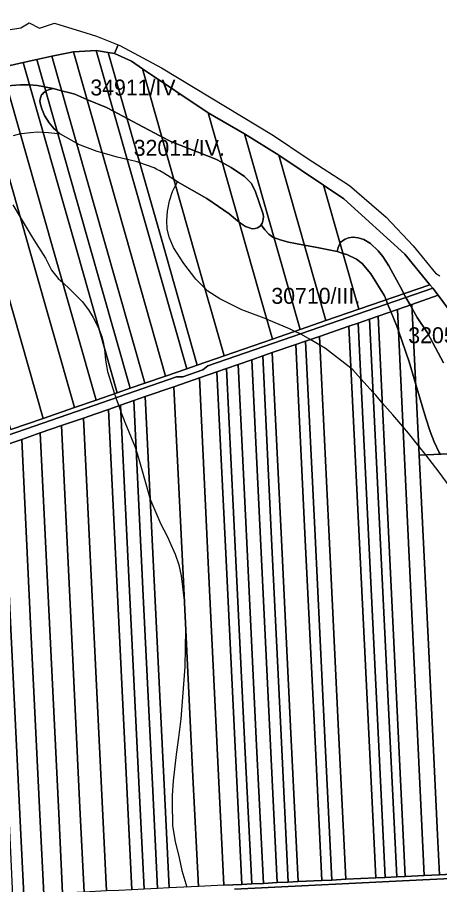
# Model space of a CAD drawing. Extents: x -521939 to -516426, y -1197857 to -1189551.
# Drawn here: x -520134 to -519736, y -1190609 to -1189793 of the extents above; entities that cross this region are included whole.
import ezdxf

# ---------------------------------------------------------------- set-up
doc = ezdxf.new("R2010")
doc.units = 0
for name, color, linetype in [('95560013', 7, 'Continuous'), ('95630013', 7, 'Continuous'), ('95640013', 7, 'Continuous'), ('95660013', 7, 'Continuous')]:
    doc.layers.add(name, color=color, linetype=linetype)

msp = doc.modelspace()

# ---------------------------------------------------------------- linework, layer by layer
at = {"layer": '95560013'}
for points in [[(-519994.39, -1190130.64), (-520013.93, -1190137.37), (-520052.62, -1190001.75), (-520101.68, -1189829.78), (-520081.3, -1189825.57), (-520032.2, -1189997.92)], [(-519974.5, -1190123.76), (-519994.39, -1190130.64), (-520032.2, -1189997.92), (-520081.3, -1189825.57), (-520059.78, -1189824.56), (-520011.22, -1189994.93)], [(-520059.78, -1189824.56), (-520048.37, -1189826.26), (-519998.68, -1190000.59), (-519964.55, -1190120.33), (-519974.5, -1190123.76), (-520011.22, -1189994.93)], [(-520016.21, -1189841.8), (-519966.48, -1190016.23), (-519939.29, -1190111.6), (-519964.55, -1190120.33), (-519998.68, -1190000.59), (-520048.37, -1189826.26), (-520042.45, -1189827.13), (-520026.64, -1189834.56)], [(-520027.72, -1190142.13), (-520039.96, -1190146.38), (-520078.09, -1190012.6), (-520128.53, -1189835.63), (-520115.8, -1189832.85), (-520068.24, -1189999.85)], [(-520013.93, -1190137.37), (-520027.72, -1190142.13), (-520068.24, -1189999.85), (-520115.8, -1189832.85), (-520101.68, -1189829.78), (-520052.62, -1190001.75)], [(-520170.1, -1189845.48), (-520148.93, -1189840.36), (-520099.85, -1190012.63), (-520059.79, -1190153.24), (-520080.27, -1190160.27), (-520121.1, -1190017.19)], [(-520078.09, -1190012.6), (-520039.96, -1190146.38), (-520059.79, -1190153.24), (-520099.85, -1190012.63), (-520148.93, -1189840.36), (-520128.53, -1189835.63)], [(-519893.79, -1190095.91), (-519939.29, -1190111.6), (-519966.48, -1190016.23), (-520016.21, -1189841.8), (-519954.44, -1189883.11), (-519905.92, -1190053.35)], [(-520109.85, -1190170.52), (-520140.18, -1190180.98), (-520187.21, -1190016.15), (-520236.34, -1189843.96), (-520214.4, -1189848.97), (-520201.29, -1189849.7), (-520152.05, -1190022.46)], [(-520201.29, -1189849.7), (-520197.95, -1189849.92), (-520181.77, -1189848.28), (-520170.1, -1189845.48), (-520121.1, -1190017.19), (-520080.27, -1190160.27), (-520109.85, -1190170.52), (-520152.05, -1190022.46)], [(-519867.74, -1190086.89), (-519893.79, -1190095.91), (-519905.92, -1190053.35), (-519954.44, -1189883.11), (-519920.2, -1189902.73)], [(-519920.2, -1189902.73), (-519887.92, -1189922.82), (-519843.42, -1190078.49), (-519867.74, -1190086.89)], [(-519812.48, -1190067.72), (-519843.42, -1190078.49), (-519887.92, -1189922.82), (-519845.8, -1189951.09)], [(-519745.61, -1190044.71), (-519812.48, -1190067.72), (-519845.8, -1189951.09), (-519826.71, -1189964.04), (-519769.14, -1190015.86)], [(-519737.67, -1190054.66), (-519717.63, -1190081.69), (-519692.57, -1190119.33), (-519690.61, -1190124.71), (-519691.71, -1190131.91), (-519714.39, -1190170.65), (-519713.62, -1190184.5), (-519709.23, -1190202.58), (-519715.93, -1190202.95), (-519727.94, -1190203.65), (-519755.55, -1190205.15), (-519762.5, -1190063.2)], [(-519768.71, -1190601.2), (-519785.79, -1190251), (-519794.41, -1190074.26), (-519785.22, -1190071.01), (-519776.17, -1190067.93), (-519750.81, -1190600.31)], [(-519776.17, -1190067.93), (-519762.5, -1190063.2), (-519755.55, -1190205.15), (-519747.01, -1190383.02), (-519738.41, -1190562.14), (-519736.61, -1190599.63), (-519750.81, -1190600.31)], [(-519793.61, -1190256.71), (-519784.84, -1190436.43), (-519776.78, -1190601.6), (-519787.62, -1190602.12), (-519795.52, -1190440.08), (-519804.28, -1190260.4), (-519813.04, -1190080.72), (-519802.38, -1190076.99)], [(-519776.78, -1190601.6), (-519784.84, -1190436.43), (-519793.61, -1190256.71), (-519802.38, -1190076.99), (-519794.41, -1190074.26), (-519785.79, -1190251), (-519768.71, -1190601.2)], [(-519821.87, -1190083.74), (-519813.16, -1190262.35), (-519804.45, -1190440.96), (-519796.57, -1190602.55), (-519824.74, -1190603.91), (-519831.84, -1190457.96), (-519841.06, -1190268.43), (-519849.58, -1190093.29)], [(-519813.04, -1190080.72), (-519804.28, -1190260.4), (-519795.52, -1190440.08), (-519787.62, -1190602.12), (-519796.57, -1190602.55), (-519804.45, -1190440.96), (-519813.16, -1190262.35), (-519821.87, -1190083.74)], [(-519831.84, -1190457.96), (-519824.74, -1190603.91), (-519837.89, -1190604.57), (-519844.74, -1190464.08), (-519853.67, -1190280.93), (-519862.6, -1190097.78), (-519849.58, -1190093.29), (-519841.06, -1190268.43)], [(-519871.89, -1190101.04), (-519863.24, -1190278.4), (-519854.65, -1190454.53), (-519847.31, -1190605.03), (-519869.68, -1190606.1), (-519876.8, -1190460.09), (-519885.36, -1190284.55), (-519893.94, -1190108.6)], [(-519862.6, -1190097.78), (-519853.67, -1190280.93), (-519844.74, -1190464.08), (-519837.89, -1190604.57), (-519847.31, -1190605.03), (-519854.65, -1190454.53), (-519863.24, -1190278.4), (-519871.89, -1190101.04)], [(-519878.91, -1190606.55), (-519889.29, -1190607.07), (-519895.57, -1190478.17), (-519904.42, -1190296.52), (-519913.25, -1190115.28), (-519903.02, -1190111.63), (-519894.32, -1190290.22), (-519885.62, -1190468.81)], [(-519869.68, -1190606.1), (-519878.91, -1190606.55), (-519885.62, -1190468.81), (-519894.32, -1190290.22), (-519903.02, -1190111.63), (-519893.94, -1190108.6), (-519885.36, -1190284.55), (-519876.8, -1190460.09)], [(-519917.36, -1190300.23), (-519908.7, -1190478.11), (-519902.39, -1190607.72), (-519913.35, -1190608.25), (-519919.36, -1190484.84), (-519928.16, -1190304.14), (-519936.96, -1190123.44), (-519926.15, -1190119.68)], [(-519913.25, -1190115.28), (-519904.42, -1190296.52), (-519895.57, -1190478.17), (-519889.29, -1190607.07), (-519902.39, -1190607.72), (-519908.7, -1190478.11), (-519917.36, -1190300.23), (-519926.15, -1190119.68)], [(-519946.2, -1190126.69), (-519937.53, -1190303.61), (-519928.59, -1190486.04), (-519922.58, -1190608.68), (-519939.51, -1190609.57), (-519945.13, -1190493.52), (-519953.89, -1190312.63), (-519962.62, -1190132.36)], [(-519928.16, -1190304.14), (-519919.36, -1190484.84), (-519913.35, -1190608.25), (-519922.58, -1190608.68), (-519928.59, -1190486.04), (-519937.53, -1190303.61), (-519946.2, -1190126.69), (-519936.96, -1190123.44)], [(-519962.62, -1190132.36), (-519953.89, -1190312.63), (-519945.13, -1190493.52), (-519939.51, -1190609.57), (-519963.54, -1190610.7), (-519968.64, -1190507.1), (-519977.66, -1190323.87), (-519986.68, -1190140.64)], [(-519986.68, -1190140.64), (-519977.66, -1190323.87), (-519968.64, -1190507.1), (-519963.54, -1190610.7), (-519991.19, -1190612.07), (-519996.22, -1190508.35), (-520004.91, -1190329.16), (-520013.6, -1190149.97)], [(-520013.6, -1190149.97), (-520004.91, -1190329.16), (-519996.22, -1190508.35), (-519991.19, -1190612.07), (-520001.96, -1190612.59), (-520006.44, -1190520.8), (-520015.4, -1190337.22), (-520024.36, -1190153.64)], [(-520048.21, -1190161.91), (-520036.77, -1190157.93), (-520028.27, -1190332.71), (-520019.52, -1190512.63), (-520014.63, -1190613.18), (-520026.22, -1190613.75)], [(-520024.36, -1190153.64), (-520015.4, -1190337.22), (-520006.44, -1190520.8), (-520001.96, -1190612.59), (-520014.63, -1190613.18), (-520019.52, -1190512.63), (-520028.27, -1190332.71), (-520036.77, -1190157.93)], [(-520050.2, -1190614.9), (-520071.81, -1190170.12), (-520060.18, -1190166.05), (-520048.21, -1190161.91), (-520026.22, -1190613.75), (-520038.38, -1190614.32)], [(-520071.18, -1190615.91), (-520075.05, -1190536.24), (-520083.71, -1190357.96), (-520092.49, -1190177.21), (-520071.81, -1190170.12), (-520050.2, -1190614.9)], [(-520091.44, -1190616.96), (-520109.18, -1190617.83), (-520112.49, -1190549.67), (-520121.22, -1190369.9), (-520129.95, -1190190.13), (-520112.49, -1190184.08), (-520103.79, -1190362.99), (-520095.09, -1190541.9)], [(-520092.49, -1190177.21), (-520083.71, -1190357.96), (-520075.05, -1190536.24), (-520071.18, -1190615.91), (-520091.44, -1190616.96), (-520095.09, -1190541.9), (-520103.79, -1190362.99), (-520112.49, -1190184.08)], [(-520109.18, -1190617.83), (-520127.96, -1190618.79), (-520131.03, -1190555.62), (-520139.79, -1190375.37), (-520148.48, -1190196.56), (-520129.95, -1190190.13), (-520121.22, -1190369.9), (-520112.49, -1190549.67)], [(-520127.96, -1190618.79), (-520138.15, -1190619.38), (-520142.13, -1190537.41), (-520144.39, -1190490.9), (-520147.18, -1190433.47), (-520148.49, -1190406.47), (-520149.36, -1190388.6), (-520150.33, -1190368.63), (-520158.52, -1190200.01), (-520148.48, -1190196.56), (-520139.79, -1190375.37), (-520131.03, -1190555.62)], [(-519727.94, -1190203.65), (-519719.31, -1190382.05), (-519710.68, -1190560.45), (-519708.85, -1190598.28), (-519736.61, -1190599.63), (-519738.41, -1190562.14), (-519747.01, -1190383.02), (-519755.55, -1190205.15)]]:
    msp.add_lwpolyline(points, close=True, dxfattribs=at)
at = {"layer": '95630013'}
msp.add_lwpolyline([(-519717.63, -1190081.69), (-519737.67, -1190054.66), (-519742.92, -1190048.01), (-519745.61, -1190044.71), (-519769.14, -1190015.86), (-519826.71, -1189964.04), (-519845.8, -1189951.09), (-519887.92, -1189922.82), (-519920.2, -1189902.73), (-519954.44, -1189883.11), (-520016.21, -1189841.8), (-520026.64, -1189834.56), (-520042.45, -1189827.13), (-520038.96, -1189819.12), (-520037.43, -1189819.73), (-519998.21, -1189840.6), (-519892.81, -1189904.25), (-519861, -1189925.67), (-519821.23, -1189951.29), (-519786.78, -1189981.15), (-519761.19, -1190007.99), (-519740.21, -1190033.91), (-519736.08, -1190036.41)], dxfattribs=at)
at = {"layer": '95640013'}
for points in [[(-520140.61, -1189804.59), (-520130.63, -1189803.21), (-520122.95, -1189798.51), (-520113.06, -1189803.55), (-520099.05, -1189798.82), (-520069.51, -1189807.88), (-520059.38, -1189810.98), (-520038.96, -1189819.12), (-520042.45, -1189827.13), (-520048.37, -1189826.26), (-520059.78, -1189824.56), (-520081.3, -1189825.57), (-520101.68, -1189829.78), (-520115.8, -1189832.85), (-520128.53, -1189835.63), (-520148.93, -1189840.36)], [(-520140.18, -1190180.98), (-520109.85, -1190170.52), (-520080.27, -1190160.27), (-520059.79, -1190153.24), (-520039.96, -1190146.38), (-520027.72, -1190142.13), (-520013.93, -1190137.37), (-519994.39, -1190130.64), (-519974.5, -1190123.76), (-519964.55, -1190120.33), (-519939.29, -1190111.6), (-519893.79, -1190095.91), (-519867.74, -1190086.89), (-519843.42, -1190078.49), (-519812.48, -1190067.72), (-519745.61, -1190044.71), (-519742.92, -1190048.01), (-519787.45, -1190063.39), (-519954.51, -1190121.09), (-519959.21, -1190124.83), (-519978.27, -1190131.41), (-519984.27, -1190131.37), (-520061.95, -1190158.2), (-520231.96, -1190216.92)], [(-520231.96, -1190216.92), (-520061.95, -1190158.2), (-519984.27, -1190131.37), (-519978.27, -1190131.41), (-519959.21, -1190124.83), (-519954.51, -1190121.09), (-519787.45, -1190063.39), (-519742.92, -1190048.01), (-519737.67, -1190054.66), (-519762.5, -1190063.2), (-519776.17, -1190067.93), (-519785.22, -1190071.01), (-519794.41, -1190074.26), (-519802.38, -1190076.99), (-519813.04, -1190080.72), (-519821.87, -1190083.74), (-519849.58, -1190093.29), (-519862.6, -1190097.78), (-519871.89, -1190101.04), (-519893.94, -1190108.6), (-519903.02, -1190111.63), (-519913.25, -1190115.28), (-519926.15, -1190119.68), (-519936.96, -1190123.44), (-519946.2, -1190126.69), (-519962.62, -1190132.36), (-519986.68, -1190140.64), (-520013.6, -1190149.97), (-520024.36, -1190153.64), (-520036.77, -1190157.93), (-520048.21, -1190161.91), (-520060.18, -1190166.05), (-520071.81, -1190170.12), (-520092.49, -1190177.21), (-520112.49, -1190184.08), (-520129.95, -1190190.13), (-520148.48, -1190196.56)], [(-519939.51, -1190609.57), (-519922.58, -1190608.68), (-519913.35, -1190608.25), (-519902.39, -1190607.72), (-519889.29, -1190607.07), (-519878.91, -1190606.55), (-519869.68, -1190606.1), (-519847.31, -1190605.03), (-519837.89, -1190604.57), (-519824.74, -1190603.91), (-519796.57, -1190602.55), (-519787.62, -1190602.12), (-519776.78, -1190601.6), (-519768.71, -1190601.2), (-519750.81, -1190600.31), (-519736.61, -1190599.63), (-519708.85, -1190598.28), (-519697.37, -1190597.74), (-519693.24, -1190597.51), (-519688.47, -1190592.56), (-519688.62, -1190605.97), (-519693.24, -1190601.52), (-519752.34, -1190604.4), (-519929.64, -1190613.04)], [(-519929.64, -1190613.04), (-519752.34, -1190604.4), (-519693.24, -1190601.52), (-519688.62, -1190605.97), (-519688.65, -1190609.3)]]:
    msp.add_lwpolyline(points, dxfattribs=at)
at = {"layer": '95660013'}
for points in [[(-520244.78, -1189796.37), (-520218.36, -1189793.23), (-520217.67, -1189803.44), (-520212.85, -1189810.43), (-520197.6, -1189811.81), (-520167.44, -1189803.44), (-520140.61, -1189804.59), (-520130.63, -1189803.21), (-520122.95, -1189798.51), (-520113.06, -1189803.55), (-520099.05, -1189798.82), (-520069.51, -1189807.88), (-520059.38, -1189810.98), (-520038.96, -1189819.12), (-520037.43, -1189819.73), (-519998.21, -1189840.6), (-519892.81, -1189904.25), (-519861, -1189925.67), (-519821.23, -1189951.29), (-519786.78, -1189981.15), (-519761.19, -1190007.99), (-519740.21, -1190033.91), (-519736.08, -1190036.41)], [(-520144.05, -1189857.5), (-520131.11, -1189856.69), (-520122.71, -1189856.69), (-520122.52, -1189856.71), (-520115.01, -1189857.39), (-520110.12, -1189858.32), (-520108.45, -1189858.64), (-520100.32, -1189860.19), (-520103.93, -1189861), (-520107.02, -1189862.4), (-520107.32, -1189862.62), (-520109.47, -1189864.15), (-520110.17, -1189865.02), (-520111.17, -1189866.25), (-520112.33, -1189869.05), (-520112.86, -1189871.91), (-520112.33, -1189875.35), (-520110.93, -1189879.43), (-520108.31, -1189885.55), (-520104.11, -1189892.32), (-520099.27, -1189898.04), (-520096.57, -1189900.36), (-520093.44, -1189903.05), (-520095.89, -1189902.76), (-520104.58, -1189901.71), (-520109.75, -1189901.54), (-520110.57, -1189901.51), (-520115.07, -1189901.36), (-520121.72, -1189901.94), (-520130, -1189902.64), (-520131.1, -1189902.94), (-520137.82, -1189904.74)], [(-519732.61, -1190118.14), (-519747.89, -1190090.02), (-519757.69, -1190075.44), (-519762.31, -1190067.1), (-519764.15, -1190063.77), (-519768.07, -1190056.7), (-519770.05, -1190053.12), (-519771.45, -1190050.6), (-519784.16, -1190026.92), (-519789.76, -1190018.06), (-519794.31, -1190012.69), (-519801.43, -1190005.93), (-519807.84, -1190002.19), (-519810.96, -1190001.18), (-519813.21, -1190000.45), (-519817.67, -1190000), (-519817.87, -1189999.98), (-519817.99, -1190000), (-519822.07, -1190000.68), (-519825.34, -1190001.73), (-519827.9, -1190003.36), (-519829.3, -1190004.76), (-519830.1, -1190006.03), (-519830.7, -1190006.98), (-519831.87, -1190009.78), (-519832.98, -1190013.57), (-519850.18, -1190010.07), (-519863.73, -1190007.43), (-519863.95, -1190007.39), (-519872.02, -1190005.91), (-519878.64, -1190004.7), (-519886.57, -1190002.6), (-519892.37, -1190000.43), (-519893.11, -1190000.15), (-519893.32, -1190000), (-519897.31, -1189997.12), (-519900.92, -1189993.16), (-519904.3, -1189988.49), (-519903.43, -1189986.86), (-519902.85, -1189984.99), (-519902.5, -1189982.89), (-519902.38, -1189980.73), (-519902.5, -1189978.46), (-519909.96, -1189956.53), (-519913.93, -1189949.3), (-519917.38, -1189945.71), (-519919.99, -1189943), (-519932.82, -1189934.37), (-519941.11, -1189929.88), (-519947.05, -1189926.67), (-519989.51, -1189910.11), (-519998.02, -1189905.61), (-520000, -1189904.56), (-520030.68, -1189888.33), (-520043.54, -1189881.53), (-520049.93, -1189878.15), (-520068.54, -1189870.36), (-520080.02, -1189865.55), (-520084.6, -1189864.32), (-520092.43, -1189862.21), (-520094.72, -1189861.59), (-520100.32, -1189860.19), (-520108.45, -1189858.64), (-520110.12, -1189858.32), (-520115.01, -1189857.39), (-520122.52, -1189856.71), (-520122.71, -1189856.69), (-520131.11, -1189856.69), (-520144.05, -1189857.5)], [(-519726.41, -1190235.21), (-519736.87, -1190220.95), (-519749.51, -1190204.82), (-519755.97, -1190196.57), (-519765.56, -1190184.33), (-519770.92, -1190178.17), (-519780.53, -1190167.11), (-519790.44, -1190155.72), (-519796.59, -1190148.64), (-519799.02, -1190145.92), (-519810.49, -1190133.08), (-519818.05, -1190124.61), (-519819.95, -1190123.16), (-519843.94, -1190104.78), (-519849.17, -1190101.67), (-519858.25, -1190096.28), (-519866.34, -1190091.48), (-519867.39, -1190091), (-519872.66, -1190088.59), (-519877.71, -1190086.29), (-519897.31, -1190077.89), (-519899.12, -1190077.21), (-519922.73, -1190068.33), (-519943.26, -1190058.07), (-519954.69, -1190050.83), (-519957.41, -1190048.06), (-519965.89, -1190039.4), (-519977.32, -1190024.71), (-519987.12, -1190009.54), (-519990.85, -1190000.68), (-519991.02, -1190000), (-519992.95, -1189992.28), (-519993.42, -1189984.58), (-519992.72, -1189975.48), (-519990.85, -1189965.92), (-519987.82, -1189957.06), (-519984.97, -1189951.39), (-519983.21, -1189947.9), (-519986.58, -1189945.76), (-519996.04, -1189939.73), (-520000, -1189937.6), (-520002.57, -1189936.22), (-520005.14, -1189934.84), (-520018.77, -1189930.1), (-520021.24, -1189929.24), (-520029.15, -1189927.38), (-520030.57, -1189927.05), (-520040.13, -1189924.8), (-520054.19, -1189920.74), (-520058.91, -1189919.38), (-520077.11, -1189912.38), (-520078.31, -1189911.69), (-520093.44, -1189903.05), (-520095.89, -1189902.76), (-520104.58, -1189901.71), (-520109.75, -1189901.54), (-520110.57, -1189901.51), (-520115.07, -1189901.36), (-520121.72, -1189901.94), (-520130, -1189902.64), (-520131.1, -1189902.94), (-520137.82, -1189904.74)], [(-519726.41, -1190235.21), (-519736.87, -1190220.95), (-519749.51, -1190204.82), (-519755.97, -1190196.57), (-519765.56, -1190184.33), (-519770.92, -1190178.17), (-519780.53, -1190167.11), (-519790.44, -1190155.72), (-519796.59, -1190148.64), (-519799.02, -1190145.92), (-519810.49, -1190133.08), (-519818.05, -1190124.61), (-519819.95, -1190123.16), (-519843.94, -1190104.78), (-519849.17, -1190101.67), (-519858.25, -1190096.28), (-519866.34, -1190091.48), (-519867.39, -1190091), (-519872.66, -1190088.59), (-519877.71, -1190086.29), (-519897.31, -1190077.89), (-519899.12, -1190077.21), (-519922.73, -1190068.33), (-519943.26, -1190058.07), (-519954.69, -1190050.83), (-519957.41, -1190048.06), (-519965.89, -1190039.4), (-519977.32, -1190024.71), (-519987.12, -1190009.54), (-519990.85, -1190000.68), (-519991.02, -1190000), (-519992.95, -1189992.28), (-519993.42, -1189984.58), (-519992.72, -1189975.48), (-519990.85, -1189965.92), (-519987.82, -1189957.06), (-519984.97, -1189951.39), (-519983.21, -1189947.9), (-519955.51, -1189963.65), (-519944.66, -1189971.09), (-519934.51, -1189978.05), (-519928.71, -1189982.89), (-519925.16, -1189985.85), (-519924.02, -1189986.8), (-519922.05, -1189988.04), (-519919.23, -1189989.83), (-519915.5, -1189991.35), (-519912.76, -1189992.05), (-519910.14, -1189991.81), (-519907.74, -1189991.17), (-519905.53, -1189989.66), (-519904.3, -1189988.49), (-519900.92, -1189993.16), (-519897.31, -1189997.12), (-519893.32, -1190000), (-519893.11, -1190000.15), (-519892.37, -1190000.43), (-519886.57, -1190002.6), (-519878.64, -1190004.7), (-519872.02, -1190005.91), (-519863.95, -1190007.39), (-519863.73, -1190007.43), (-519850.18, -1190010.07), (-519832.98, -1190013.57), (-519827.48, -1190015.22), (-519823.65, -1190016.37), (-519814.78, -1190020.57), (-519809.42, -1190024.76), (-519801.02, -1190034.56), (-519788.42, -1190055.09), (-519786.86, -1190058.9), (-519785.32, -1190062.65), (-519782.3, -1190070.02), (-519776.76, -1190083.55), (-519775.21, -1190088), (-519765.09, -1190117.14), (-519758.81, -1190138.5), (-519749.46, -1190170.33), (-519745.21, -1190182.87), (-519741.53, -1190192.49), (-519736.69, -1190202.58), (-519735.84, -1190204.08)], [(-520138.4, -1189969.48), (-520131.36, -1189981.24), (-520120.13, -1190000), (-520118.57, -1190002.6), (-520107.61, -1190019.63), (-520101.78, -1190031.06), (-520095.48, -1190038.76), (-520091.29, -1190042.68), (-520084.75, -1190048.79), (-520073.08, -1190060.46), (-520067.02, -1190068.39), (-520062.58, -1190075.62), (-520058.15, -1190084.02), (-520056.7, -1190087.65), (-520054.42, -1190093.35), (-520052.79, -1190100.11), (-520052.15, -1190103.61), (-520051.85, -1190105.25), (-520050.92, -1190115.74), (-520049.29, -1190126.47), (-520042.44, -1190147.24), (-520041.59, -1190149.8), (-520041.16, -1190151.02), (-520039.9, -1190154.56), (-520038.48, -1190158.53), (-520036.46, -1190164.21), (-520032.96, -1190174.06), (-520022.93, -1190197.63), (-520022.07, -1190200.6), (-520021.24, -1190203.46), (-520017.79, -1190215.35), (-520008.92, -1190246.38), (-520008.46, -1190248.01), (-520000, -1190267.68), (-519999.83, -1190268.08), (-519992.37, -1190282.54), (-519990.78, -1190286.09), (-519985.37, -1190298.17), (-519981.87, -1190308.2), (-519979.77, -1190318.46), (-519976.97, -1190341.56), (-519975.57, -1190369.09), (-519976.27, -1190404.08), (-519980, -1190453.07), (-519982.29, -1190470.4), (-519984.44, -1190486.66), (-519987.24, -1190511.15), (-519988.17, -1190525.15), (-519988.17, -1190539.38), (-519988.07, -1190545.32), (-519987.94, -1190553.61), (-519985.37, -1190568.31), (-519981.8, -1190583.79), (-519979.07, -1190595.6), (-519974.48, -1190611.24)], [(-520138.4, -1189969.48), (-520131.36, -1189981.24), (-520120.13, -1190000), (-520118.57, -1190002.6), (-520107.61, -1190019.63), (-520101.78, -1190031.06), (-520095.48, -1190038.76), (-520091.29, -1190042.68), (-520084.75, -1190048.79), (-520073.08, -1190060.46), (-520067.02, -1190068.39), (-520062.58, -1190075.62), (-520058.15, -1190084.02), (-520056.7, -1190087.65), (-520054.42, -1190093.35), (-520052.79, -1190100.11), (-520052.15, -1190103.61), (-520051.85, -1190105.25), (-520050.92, -1190115.74), (-520049.29, -1190126.47), (-520042.44, -1190147.24), (-520041.59, -1190149.8), (-520041.16, -1190151.02), (-520039.9, -1190154.56), (-520038.48, -1190158.53), (-520036.46, -1190164.21), (-520032.96, -1190174.06), (-520022.93, -1190197.63), (-520022.07, -1190200.6), (-520021.24, -1190203.46), (-520017.79, -1190215.35), (-520008.92, -1190246.38), (-520008.46, -1190248.01), (-520000, -1190267.68), (-519999.83, -1190268.08), (-519992.37, -1190282.54), (-519990.78, -1190286.09), (-519985.37, -1190298.17), (-519981.87, -1190308.2), (-519979.77, -1190318.46), (-519976.97, -1190341.56), (-519975.57, -1190369.09), (-519976.27, -1190404.08), (-519980, -1190453.07), (-519982.29, -1190470.4), (-519984.44, -1190486.66), (-519987.24, -1190511.15), (-519988.17, -1190525.15), (-519988.17, -1190539.38), (-519988.07, -1190545.32), (-519987.94, -1190553.61), (-519985.37, -1190568.31), (-519981.8, -1190583.79), (-519979.07, -1190595.6), (-519974.48, -1190611.24)], [(-519735.84, -1190204.08), (-519736.69, -1190202.58), (-519741.53, -1190192.49), (-519745.21, -1190182.87), (-519749.46, -1190170.33), (-519758.81, -1190138.5), (-519765.09, -1190117.14), (-519775.21, -1190088), (-519776.76, -1190083.55), (-519782.3, -1190070.02), (-519785.32, -1190062.65), (-519786.86, -1190058.9), (-519788.42, -1190055.09), (-519801.02, -1190034.56), (-519809.42, -1190024.76), (-519814.78, -1190020.57), (-519823.65, -1190016.37), (-519827.48, -1190015.22), (-519832.98, -1190013.57), (-519831.87, -1190009.78), (-519830.7, -1190006.98), (-519830.1, -1190006.03), (-519829.3, -1190004.76), (-519827.9, -1190003.36), (-519825.34, -1190001.73), (-519822.07, -1190000.68), (-519817.99, -1190000), (-519817.87, -1189999.98), (-519817.67, -1190000), (-519813.21, -1190000.45), (-519810.96, -1190001.18), (-519807.84, -1190002.19), (-519801.43, -1190005.93), (-519794.31, -1190012.69), (-519789.76, -1190018.06), (-519784.16, -1190026.92), (-519771.45, -1190050.6), (-519770.05, -1190053.12), (-519768.07, -1190056.7), (-519764.15, -1190063.77), (-519762.31, -1190067.1), (-519757.69, -1190075.44), (-519747.89, -1190090.02), (-519732.61, -1190118.14)]]:
    msp.add_lwpolyline(points, dxfattribs=at)
msp.add_lwpolyline([(-519910.14, -1189991.81), (-519912.76, -1189992.05), (-519915.5, -1189991.35), (-519919.23, -1189989.83), (-519922.05, -1189988.04), (-519924.02, -1189986.8), (-519925.16, -1189985.85), (-519928.71, -1189982.89), (-519934.51, -1189978.05), (-519944.66, -1189971.09), (-519955.51, -1189963.65), (-519983.21, -1189947.9), (-519986.58, -1189945.76), (-519996.04, -1189939.73), (-520000, -1189937.6), (-520002.57, -1189936.22), (-520005.14, -1189934.84), (-520018.77, -1189930.1), (-520021.24, -1189929.24), (-520029.15, -1189927.38), (-520030.57, -1189927.05), (-520040.13, -1189924.8), (-520054.19, -1189920.74), (-520058.91, -1189919.38), (-520077.11, -1189912.38), (-520078.31, -1189911.69), (-520093.44, -1189903.05), (-520096.57, -1189900.36), (-520099.27, -1189898.04), (-520104.11, -1189892.32), (-520108.31, -1189885.55), (-520110.93, -1189879.43), (-520112.33, -1189875.35), (-520112.86, -1189871.91), (-520112.33, -1189869.05), (-520111.17, -1189866.25), (-520110.17, -1189865.02), (-520109.47, -1189864.15), (-520107.32, -1189862.62), (-520107.02, -1189862.4), (-520103.93, -1189861), (-520100.32, -1189860.19), (-520094.72, -1189861.59), (-520092.43, -1189862.21), (-520084.6, -1189864.32), (-520080.02, -1189865.55), (-520068.54, -1189870.36), (-520049.93, -1189878.15), (-520043.54, -1189881.53), (-520030.68, -1189888.33), (-520000, -1189904.56), (-519998.02, -1189905.61), (-519989.51, -1189910.11), (-519947.05, -1189926.67), (-519941.11, -1189929.88), (-519932.82, -1189934.37), (-519919.99, -1189943), (-519917.38, -1189945.71), (-519913.93, -1189949.3), (-519909.96, -1189956.53), (-519902.5, -1189978.46), (-519902.38, -1189980.73), (-519902.5, -1189982.89), (-519902.85, -1189984.99), (-519903.43, -1189986.86), (-519904.3, -1189988.49), (-519905.53, -1189989.66), (-519907.74, -1189991.17)], close=True, dxfattribs=at)

# ---------------------------------------------------------------- texts
for s, rotation, p in [('34911/IV.', 360, (-520065.29, -1189866.71)), ('32011/IV.', 0, (-520024.48, -1189923.44)), ('32051/IV.', 360, (-519765.91, -1190099.72))]:
    msp.add_text(s, height=15, rotation=rotation, dxfattribs=at).set_placement(p)
msp.add_text('30710/III.', height=15, dxfattribs=at).set_placement((-519894.85, -1190062.63))

doc.saveas('drawing.dxf')
